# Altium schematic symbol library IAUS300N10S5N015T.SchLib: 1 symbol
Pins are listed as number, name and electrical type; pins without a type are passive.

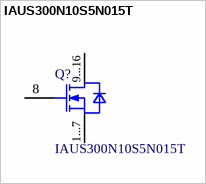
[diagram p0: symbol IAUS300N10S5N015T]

## IAUS300N10S5N015T
designator Q?
Insulated-Gate Field-Effect Transistor (IGFET), N-Channel, Enhancement, Body Diode, Pin 1 Source, 2 Source, 3 Source , 4 Source, 5 Source, 6 Source, 7 Source, 8 Gate, 9 Drain, 10 Drain, 11 Drain, 12 Drain, 13 Drain, 14 Drain, 15 Drain, 16 Drain, 16 Pins; Manufacturer: Infineon Technologies
pins: 1 SOURCE1, 2 SOURCE2, 3 SOURCE3, 4 SOURCE4, 5 SOURCE5, 6 SOURCE6, 7 SOURCE7, 8 GATE, 9 DRAIN1, 10 DRAIN2, 11 DRAIN3, 12 DRAIN4, 13 DRAIN5, 14 DRAIN6, 15 DRAIN7, 16 DRAIN8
